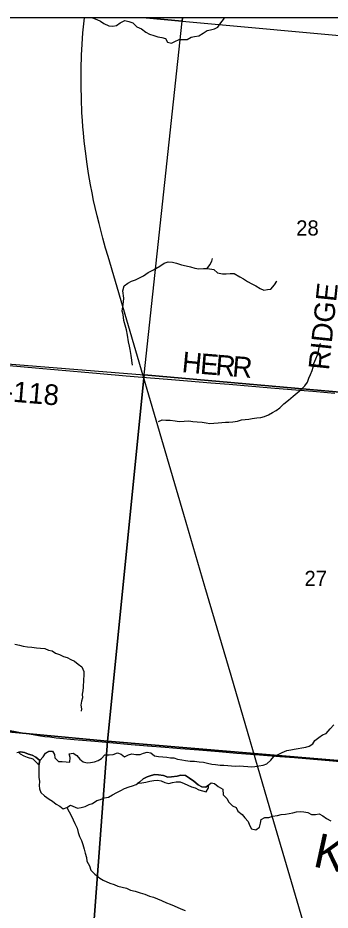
# Model space of a CAD drawing. Extents: x 0 to 1067, y 0 to 440.
# Drawn here: x 800.649 to 801.512, y 355.137 to 357.602 of the extents above; entities that cross this region are included whole.
import ezdxf

# ---------------------------------------------------------------- set-up
doc = ezdxf.new("R2010")
doc.units = 0
for name, color, linetype in [('GM_X_Minor_Lake', 7, 'Continuous'), ('GM_X_Minor_River', 7, 'Continuous'), ('GM_X_Minor_River_Text', 7, 'Continuous'), ('GM_X_Rail_Line', 7, 'Continuous'), ('GM_X_Section', 7, 'Continuous'), ('GM_X_Section_Text', 7, 'Continuous'), ('GM_X_State_Route', 7, 'Continuous'), ('GM_X_Township_Road', 7, 'Continuous'), ('GM_X_Township_Road_Text', 7, 'Continuous'), ('GM_X_US_Shield', 7, 'Continuous')]:
    doc.layers.add(name, color=color, linetype=linetype)

msp = doc.modelspace()

# ---------------------------------------------------------------- linework, layer by layer
at = {"layer": 'GM_X_Minor_Lake'}
for points in [[(800.7098, 355.55), (800.6994, 355.5591), (800.6886, 355.5647), (800.6784, 355.5677), (800.6679, 355.5722), (800.6566, 355.5744), (800.6508, 355.5733)], [(800.6508, 355.5733), (800.6556, 355.5686), (800.6654, 355.5633), (800.6703, 355.5614), (800.6753, 355.5594), (800.6802, 355.5578), (800.6855, 355.5564), (800.6905, 355.5548), (800.695, 355.5499), (800.6998, 355.5452), (800.7047, 355.5412), (800.7076, 355.5388)], [(800.7076, 355.5388), (800.7098, 355.55)], [(801.1755, 355.4823), (801.1687, 355.4766), (801.1574, 355.4774), (801.1473, 355.4826), (801.1354, 355.4929), (801.1232, 355.5012), (801.112, 355.5084), (801.0991, 355.5096), (801.0892, 355.5072), (801.0739, 355.505), (801.0637, 355.5045), (801.052, 355.5083), (801.0377, 355.511), (801.0274, 355.5113), (801.0171, 355.5089), (801.0064, 355.5054), (800.9956, 355.4993), (800.9855, 355.4901), (800.9795, 355.4863)], [(800.9795, 355.4863), (800.982, 355.4875), (800.9915, 355.4884), (801.0029, 355.4907), (801.0136, 355.4927), (801.0247, 355.495), (801.035, 355.4962), (801.0451, 355.4936), (801.0553, 355.4895), (801.0662, 355.4869), (801.0761, 355.4893), (801.0864, 355.4913), (801.0974, 355.4909), (801.1083, 355.4868), (801.1184, 355.4823), (801.1289, 355.4771), (801.1391, 355.4749), (801.1492, 355.4696), (801.1593, 355.4663), (801.1699, 355.464), (801.1759, 355.4745), (801.1755, 355.4823)]]:
    msp.add_lwpolyline(points, dxfattribs=at)
at = {"layer": 'GM_X_Minor_River'}
for points in [[(800.8555, 357.6021), (800.8557, 357.6018), (800.8673, 357.5976), (800.8774, 357.5932), (800.8871, 357.5868), (800.9009, 357.5804), (800.9115, 357.5793), (800.9222, 357.5813), (800.9323, 357.5885), (800.945, 357.595), (800.9555, 357.592), (800.9672, 357.5882), (800.9783, 357.5777), (800.9906, 357.5713), (801.0029, 357.5626), (801.0133, 357.5574), (801.025, 357.5529), (801.0355, 357.5499), (801.0468, 357.5477), (801.057, 357.5451), (801.0628, 357.5351), (801.0737, 357.5325), (801.0833, 357.5372), (801.0945, 357.5425), (801.1062, 357.5422), (801.1172, 357.5422), (801.1277, 357.5483), (801.1376, 357.5503), (801.1494, 357.5522), (801.1607, 357.5598), (801.1719, 357.5671), (801.1818, 357.5694), (801.1921, 357.5714), (801.2021, 357.5768), (801.2101, 357.5883), (801.2176, 357.5979), (801.2199, 357.6021)], [(800.9661, 356.6428), (800.9623, 356.6691), (800.9594, 356.6859), (800.9578, 356.6954), (800.9551, 356.7065), (800.9526, 356.7256), (800.9492, 356.7401), (800.9454, 356.7528), (800.942, 356.7661), (800.9398, 356.7821), (800.9371, 356.7917), (800.9393, 356.8038), (800.9413, 356.8174), (800.9419, 356.8272), (800.9395, 356.8478), (800.943, 356.8617), (800.9527, 356.8694), (800.9634, 356.8744), (800.9738, 356.8787), (800.9834, 356.8829), (800.9961, 356.889), (801.0093, 356.8985), (801.024, 356.906), (801.0413, 356.9158), (801.0537, 356.9245), (801.0645, 356.9284), (801.0762, 356.9273), (801.0871, 356.9247), (801.101, 356.9201), (801.1138, 356.9167), (801.1263, 356.914), (801.1379, 356.9107), (801.1489, 356.9084), (801.1618, 356.9096), (801.1732, 356.91), (801.1902, 356.9068), (801.2009, 356.8978), (801.2149, 356.8947), (801.2251, 356.8948), (801.2358, 356.8957), (801.2464, 356.8953), (801.2624, 356.8865), (801.2725, 356.8813), (801.2833, 356.8734), (801.2957, 356.8673), (801.3065, 356.8617), (801.3184, 356.8545), (801.3289, 356.8497), (801.3385, 356.8517), (801.3484, 356.8529), (801.3586, 356.8647), (801.3642, 356.8748), (801.3649, 356.8744)], [(801.1719, 356.91), (801.1796, 356.9201), (801.1848, 356.9301), (801.1865, 356.9373)], [(801.0382, 356.4872), (801.0482, 356.4911), (801.0584, 356.4904), (801.0702, 356.4908), (801.0837, 356.4885), (801.0947, 356.4871), (801.1088, 356.4882), (801.1213, 356.4886), (801.1327, 356.4871), (801.1448, 356.486), (801.158, 356.4852), (801.169, 356.483), (801.1796, 356.4815), (801.191, 356.4823), (801.2024, 356.4835), (801.2127, 356.4844), (801.2229, 356.4848), (801.2324, 356.4853), (801.2427, 356.4858), (801.256, 356.488), (801.2671, 356.4915), (801.2774, 356.4923), (801.2873, 356.4932), (801.2968, 356.4948), (801.309, 356.4967), (801.3208, 356.4979), (801.3304, 356.5007), (801.3415, 356.5056), (801.3527, 356.5114), (801.3624, 356.5172), (801.3725, 356.5249), (801.3842, 356.5355), (801.3966, 356.5458), (801.4095, 356.5572), (801.4211, 356.5664), (801.432, 356.5752), (801.4422, 356.5851), (801.4493, 356.5959), (801.4534, 356.6068), (801.4575, 356.6166), (801.462, 356.6275), (801.4646, 356.6373), (801.4668, 356.6471), (801.4721, 356.6602), (801.4766, 356.6707), (801.4795, 356.6813), (801.4817, 356.6914), (801.4843, 356.7012), (801.4851, 356.7024)], [(800.6414, 355.8714), (800.6538, 355.8687), (800.6644, 355.8661), (800.6761, 355.8646), (800.6875, 355.8636), (800.7011, 355.8616), (800.7121, 355.8605), (800.7238, 355.8598), (800.7339, 355.8553), (800.7437, 355.8535), (800.7534, 355.8471), (800.7639, 355.8427), (800.7751, 355.8378), (800.7857, 355.8352), (800.7958, 355.8295), (800.8055, 355.8251), (800.8159, 355.8168), (800.8259, 355.8088), (800.8312, 355.7958), (800.8317, 355.7862), (800.8302, 355.7729), (800.8296, 355.7532), (800.8285, 355.7429), (800.8271, 355.7331), (800.8276, 355.7235), (800.825, 355.7137), (800.8236, 355.7031), (800.8248, 355.6932), (800.8238, 355.6864)], [(801.2729, 355.5341), (801.2842, 355.5334), (801.2937, 355.5331), (801.3036, 355.5332), (801.3147, 355.5359), (801.3269, 355.5374), (801.3372, 355.5413), (801.3485, 355.5509), (801.356, 355.5617), (801.3668, 355.5663), (801.3791, 355.5724), (801.3918, 355.5781), (801.4029, 355.5801), (801.4128, 355.5817), (801.4235, 355.5833), (801.4341, 355.5853), (801.4444, 355.5872), (801.454, 355.5896), (801.464, 355.5958), (801.4693, 355.6059), (801.4809, 355.6136), (801.491, 355.6213), (801.5013, 355.6251), (801.5116, 355.6374), (801.5218, 355.6489)], [(800.6463, 355.5725), (800.6566, 355.5744), (800.6679, 355.5722), (800.6784, 355.5677), (800.6886, 355.5647), (800.6994, 355.5591), (800.7098, 355.55), (800.7196, 355.5604), (800.7252, 355.5701), (800.7348, 355.5756), (800.7447, 355.5764), (800.7505, 355.5667), (800.7514, 355.5572), (800.7617, 355.5477), (800.7716, 355.5471), (800.7829, 355.5463), (800.7928, 355.546), (800.7935, 355.5586), (800.7912, 355.5686), (800.8019, 355.5705), (800.8119, 355.5638), (800.8203, 355.554), (800.83, 355.5468), (800.8405, 355.5439), (800.8501, 355.5447), (800.8611, 355.5463), (800.8711, 355.5506), (800.8807, 355.556), (800.8898, 355.5656), (800.9019, 355.5657), (800.9126, 355.5669), (800.9248, 355.5718), (800.9346, 355.5673), (800.9443, 355.5606), (800.9546, 355.5656), (800.9642, 355.5684), (800.9752, 355.5669), (800.9869, 355.5666), (800.9965, 355.5701), (801.0065, 355.5732), (801.017, 355.571), (801.0267, 355.5631), (801.0376, 355.5616), (801.0498, 355.5605), (801.0607, 355.559), (801.0705, 355.5572), (801.08, 355.5573), (801.0905, 355.5536), (801.1019, 355.5517), (801.1121, 355.5503), (801.1249, 355.5488), (801.1374, 355.548), (801.1499, 355.5461), (801.1624, 355.5454), (801.173, 355.5431), (801.185, 355.5405), (801.1948, 355.5391), (801.2081, 355.5375), (801.2183, 355.5376), (801.2293, 355.5365), (801.2392, 355.5358), (801.2505, 355.5347), (801.2623, 355.5352), (801.2729, 355.5341)], [(800.7098, 355.55), (800.7071, 355.5364), (800.7075, 355.5242), (800.7072, 355.5136), (800.7073, 355.504), (800.7089, 355.4918), (800.7086, 355.4815), (800.7094, 355.4716), (800.7125, 355.462), (800.7225, 355.4522), (800.7355, 355.4438), (800.7452, 355.4378), (800.7549, 355.4299), (800.7649, 355.4243), (800.7746, 355.4171), (800.7846, 355.4203), (800.795, 355.4264), (800.8145, 355.4182), (800.824, 355.4206), (800.8355, 355.4233), (800.8463, 355.4287), (800.8558, 355.4311), (800.8679, 355.4395), (800.8778, 355.4426), (800.8889, 355.4469), (800.8993, 355.4492), (800.9108, 355.455), (800.9224, 355.4615), (800.9339, 355.4676), (800.9436, 355.4727), (800.9566, 355.4776), (800.9662, 355.4804), (800.9758, 355.4839), (800.9855, 355.4901), (800.9956, 355.4993), (801.0064, 355.5054), (801.0171, 355.5089), (801.0274, 355.5113), (801.0377, 355.511), (801.052, 355.5083), (801.0637, 355.5045), (801.0739, 355.505), (801.0892, 355.5072), (801.0991, 355.5096), (801.112, 355.5084), (801.1232, 355.5012), (801.1354, 355.4929), (801.1473, 355.4826), (801.1574, 355.4774), (801.1687, 355.4766), (801.1831, 355.4888), (801.1929, 355.487), (801.2026, 355.4783), (801.2152, 355.4707), (801.2167, 355.455), (801.2263, 355.4456), (801.232, 355.4348), (801.2424, 355.4253), (801.2521, 355.4205), (801.2571, 355.4101), (801.2686, 355.4013), (801.2759, 355.3916), (801.2855, 355.3814), (801.2894, 355.3718), (801.2944, 355.3614), (801.3068, 355.3587), (801.3165, 355.366), (801.3191, 355.377), (801.3217, 355.3876), (801.3314, 355.3926), (801.3427, 355.3923), (801.3523, 355.3962), (801.3661, 355.3981), (801.3768, 355.4008), (801.3882, 355.402), (801.3985, 355.4039), (801.4092, 355.4055), (801.4191, 355.4087), (801.429, 355.4095), (801.4392, 355.4084), (801.4498, 355.4062), (801.4603, 355.4013), (801.4713, 355.4014), (801.4812, 355.403), (801.4917, 355.3977), (801.5017, 355.3902), (801.5136, 355.3838)], [(800.7842, 355.4202), (800.7907, 355.4087), (800.7964, 355.3982), (800.8022, 355.3866), (800.8068, 355.3762), (800.8133, 355.3631), (800.8163, 355.3512), (800.8198, 355.3404), (800.8248, 355.3296), (800.8286, 355.3177), (800.8321, 355.305), (800.8355, 355.2943), (800.839, 355.282), (800.8398, 355.2717), (800.8474, 355.2589), (800.8508, 355.247), (800.8623, 355.236), (800.8756, 355.2249), (800.8853, 355.2197), (800.9029, 355.2115), (800.9154, 355.2077), (800.9251, 355.2033), (800.9492, 355.1972), (800.9601, 355.1923), (800.9729, 355.1893), (800.9868, 355.1843), (800.9999, 355.1805), (801.0127, 355.1752), (801.024, 355.1729), (801.0349, 355.1676), (801.0457, 355.1635), (801.0596, 355.1574), (801.0697, 355.1529), (801.0806, 355.1484), (801.0993, 355.1406), (801.1113, 355.1357)]]:
    msp.add_lwpolyline(points, dxfattribs=at)
at = {"layer": 'GM_X_Rail_Line'}
msp.add_lwpolyline([(801.4633, 355.0166), (801.4053, 355.2149), (801.352, 355.3966), (801.2383, 355.7855), (801.1659, 356.031), (801.1081, 356.23), (800.8989, 356.9426), (800.8918, 356.9659), (800.8839, 356.9938), (800.8782, 357.0155), (800.8735, 357.0336), (800.8683, 357.0548), (800.8627, 357.0781), (800.8585, 357.0978), (800.8544, 357.1182), (800.8503, 357.1405), (800.8448, 357.1721), (800.8408, 357.1978), (800.836, 357.2338), (800.8328, 357.2618), (800.8305, 357.2844), (800.8291, 357.3009), (800.8277, 357.3186), (800.8264, 357.3401), (800.8248, 357.3783), (800.8239, 357.4122), (800.8241, 357.461), (800.8253, 357.4986), (800.8269, 357.5294), (800.829, 357.561), (800.8314, 357.5858), (800.833, 357.6021)], dxfattribs=at)
at = {"layer": 'GM_X_Section'}
for points in [[(802.1444, 357.4983), (802.0488, 356.5225), (800.9985, 356.6154), (801.1031, 357.5929)], [(800.9985, 356.6154), (800.8971, 355.6038), (799.8698, 355.7001), (799.9676, 356.6989)], [(800.9985, 356.6154), (802.0488, 356.5225), (801.949, 355.5154), (800.8971, 355.6038)], [(799.8698, 355.7001), (800.8971, 355.6038), (800.8205, 354.5819), (799.7802, 354.7186)], [(800.8971, 355.6038), (801.949, 355.5154), (801.8528, 354.4938), (800.8205, 354.5819)]]:
    msp.add_lwpolyline(points, close=True, dxfattribs=at)
at = {"layer": 'GM_X_State_Route'}
msp.add_lwpolyline([(800.6146, 355.6354), (800.6563, 355.6277), (800.6857, 355.6227), (800.712, 355.6186), (800.7239, 355.6169), (800.7377, 355.6152), (800.7552, 355.6132), (800.8052, 355.6083), (800.8622, 355.6032), (800.9024, 355.5998), (800.9624, 355.5945), (801.007, 355.5908), (801.056, 355.587), (801.0987, 355.5835), (801.1489, 355.5796), (801.2046, 355.5751), (801.2541, 355.5709), (801.3167, 355.5659), (801.373, 355.5613), (801.4133, 355.5582), (801.4659, 355.5537), (801.5093, 355.5502), (801.5601, 355.546)], dxfattribs=at)
at = {"layer": 'GM_X_Township_Road'}
for points in [[(804.8401, 353.205), (804.8401, 357.6021), (800.0635, 357.6021)], [(800.5047, 356.6515), (800.5122, 356.6508), (800.6465, 356.6393), (800.7183, 356.6329), (800.8242, 356.6241), (800.8762, 356.6198), (800.9486, 356.6134), (800.9931, 356.6095), (801.0625, 356.6042), (801.1176, 356.5993), (801.1826, 356.5938), (801.2333, 356.5896), (801.3476, 356.5796), (801.428, 356.5736), (801.4645, 356.5703), (801.5246, 356.5652)]]:
    msp.add_lwpolyline(points, dxfattribs=at)
at = {"layer": 'GM_X_US_Shield'}
for points in [[(801.0038, 357.6021), (800.056, 357.6021), (799.9676, 356.6989), (800.9985, 356.6154), (801.1031, 357.5929)], [(801.1042, 357.6021), (801.0038, 357.6021), (801.1031, 357.5929)], [(802.1539, 357.6021), (801.1042, 357.6021), (801.1031, 357.5929), (802.1444, 357.4983)]]:
    msp.add_lwpolyline(points, close=True, dxfattribs=at)

# ---------------------------------------------------------------- texts
at = {"layer": 'GM_X_Minor_River_Text'}
msp.add_text('Kings', height=0.0947, rotation=347.6289, dxfattribs=at).set_placement((801.4615, 355.2582))
at = {"layer": 'GM_X_Section_Text'}
for s, p in [('28', (801.4181, 357.0007)), ('27', (801.441, 356.0324))]:
    msp.add_text(s, height=0.04186, rotation=0, dxfattribs=at).set_placement(p)
at = {"layer": 'GM_X_Township_Road_Text'}
for s, height, rotation, p in [('RIDGE', 0.05682, 84.001, (801.5084, 356.6272)), ('H', 0.0568, 354.4032, (801.1005, 356.6236)), ('E', 0.0568, 355.3054, (801.1512, 356.6187)), ('R', 0.0568, 355.3308, (801.1936, 356.6152)), ('R', 0.0568, 355.3268, (801.2401, 356.6114)), ('T-118', 0.05682, 355.2365, (800.5628, 356.5474))]:
    msp.add_text(s, height=height, rotation=rotation, dxfattribs=at).set_placement(p)

doc.saveas('drawing.dxf')
